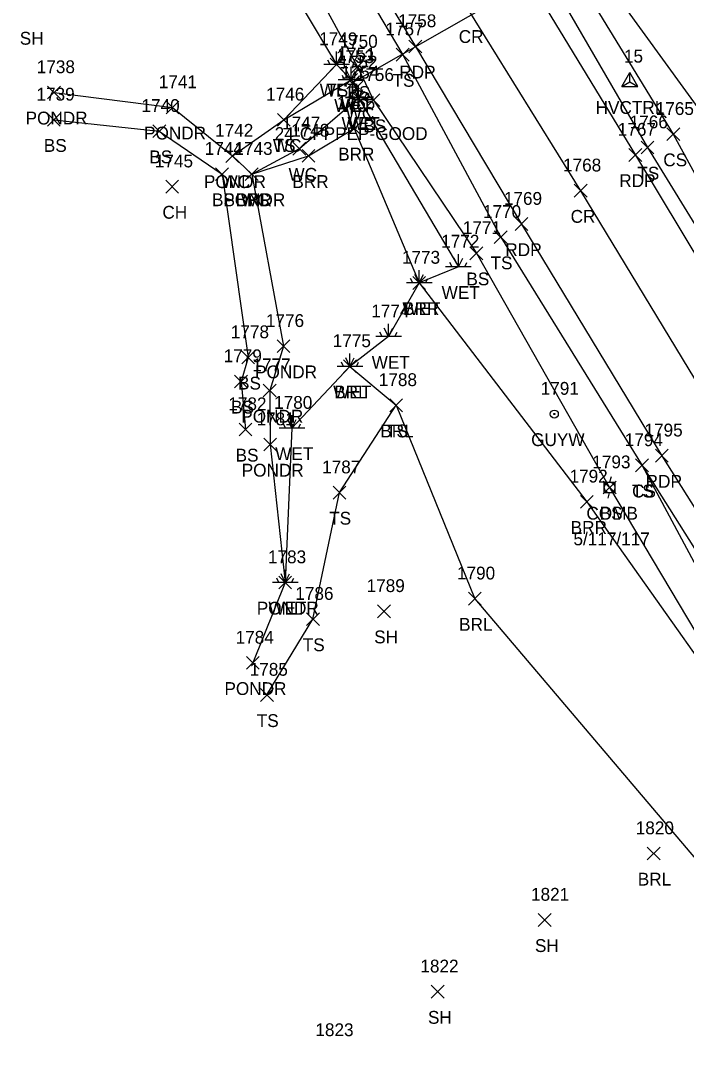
# Model space of a CAD drawing. Extents: x 1501299 to 1502485, y 381423 to 383765.
# Drawn here: x 1501313.7 to 1501417.5, y 383498.2 to 383658 of the extents above; entities that cross this region are included whole.
import ezdxf

# ---------------------------------------------------------------- set-up
doc = ezdxf.new("R2010")
doc.units = 0
for name, color, linetype in [('C_A', 7, 'Continuous'), ('C_I', 7, 'Continuous'), ('CPSM', 7, 'Continuous'), ('D_A', 7, 'Continuous'), ('D_C', 7, 'Continuous'), ('D_I', 7, 'Continuous'), ('D_TIC', 7, 'Continuous'), ('DCP', 7, 'Continuous'), ('L_A', 7, 'Continuous'), ('L_I', 7, 'Continuous'), ('L_TIC', 7, 'Continuous'), ('LABL', 7, 'Continuous'), ('LAWE', 7, 'Continuous'), ('LELB', 7, 'Continuous'), ('LWET', 7, 'Continuous'), ('P_A', 7, 'Continuous'), ('P_I', 7, 'Continuous'), ('P_TIC', 7, 'Continuous'), ('PET', 7, 'Continuous'), ('PRC', 7, 'Continuous'), ('U_A', 7, 'Continuous'), ('U_C', 7, 'Continuous'), ('U_I', 7, 'Continuous'), ('UP', 7, 'Continuous'), ('UPGW', 7, 'Continuous')]:
    doc.layers.add(name, color=color, linetype=linetype)

msp = doc.modelspace()

# ---------------------------------------------------------------- linework, layer by layer
at = {"layer": 'CPSM'}
for p, q in [((1501407.42, 383647.74), (1501408.67, 383649.91)), ((1501409.92, 383647.74), (1501408.67, 383649.91)), ((1501408.67, 383648.46), (1501408.67, 383649.91)), ((1501407.42, 383647.74), (1501408.67, 383648.46)), ((1501408.67, 383648.46), (1501408.67, 383648.46)), ((1501408.67, 383648.46), (1501409.92, 383647.74)), ((1501407.42, 383647.74), (1501409.92, 383647.74))]:
    msp.add_line(p, q, dxfattribs=at)
at = {"layer": 'D_TIC'}
for points in [[(1501364.58, 383647.39), (1501366.58, 383649.39)], [(1501366.58, 383647.39), (1501364.58, 383649.39)]]:
    msp.add_lwpolyline(points, dxfattribs=at)
at = {"layer": 'DCP'}
msp.add_lwpolyline([(1501365.58, 383648.39), (1501401.54, 383668.95)], dxfattribs=at)
at = {"layer": 'L_TIC'}
for points in [[(1501372.29, 383651.69), (1501374.29, 383653.69)], [(1501374.29, 383651.69), (1501372.29, 383653.69)], [(1501361.98, 383650.17), (1501363.98, 383652.17)], [(1501363.98, 383650.17), (1501361.98, 383652.17)], [(1501365.23, 383649.78), (1501367.23, 383651.78)], [(1501367.23, 383649.78), (1501365.23, 383651.78)], [(1501364.24, 383647.78), (1501366.24, 383649.78)], [(1501366.24, 383647.78), (1501364.24, 383649.78)], [(1501365.1, 383646.54), (1501367.1, 383648.54)], [(1501367.1, 383646.54), (1501365.1, 383648.54)], [(1501317.96, 383645.81), (1501319.96, 383647.81)], [(1501319.96, 383645.81), (1501317.96, 383647.81)], [(1501365.39, 383644.96), (1501367.39, 383646.96)], [(1501367.39, 383644.96), (1501365.39, 383646.96)], [(1501365.39, 383644.96), (1501367.39, 383646.96)], [(1501367.39, 383644.96), (1501365.39, 383646.96)], [(1501336.42, 383643.47), (1501338.42, 383645.47)], [(1501338.42, 383643.47), (1501336.42, 383645.47)], [(1501367.72, 383644.59), (1501369.72, 383646.59)], [(1501369.72, 383644.59), (1501367.72, 383646.59)], [(1501317.93, 383641.54), (1501319.93, 383643.54)], [(1501319.93, 383641.54), (1501317.93, 383643.54)], [(1501353.76, 383641.54), (1501355.76, 383643.54)], [(1501355.76, 383641.54), (1501353.76, 383643.54)], [(1501353.76, 383641.54), (1501355.76, 383643.54)], [(1501355.76, 383641.54), (1501353.76, 383643.54)], [(1501364.75, 383640.19), (1501366.75, 383642.19)], [(1501366.75, 383640.19), (1501364.75, 383642.19)], [(1501334.37, 383639.76), (1501336.37, 383641.76)], [(1501336.37, 383639.76), (1501334.37, 383641.76)], [(1501414.46, 383639.29), (1501416.46, 383641.29)], [(1501416.46, 383639.29), (1501414.46, 383641.29)], [(1501356.19, 383637.04), (1501358.19, 383639.04)], [(1501358.19, 383637.04), (1501356.19, 383639.04)], [(1501410.45, 383637.21), (1501412.45, 383639.21)], [(1501412.45, 383637.21), (1501410.45, 383639.21)], [(1501345.75, 383635.9), (1501347.75, 383637.9)], [(1501347.75, 383635.9), (1501345.75, 383637.9)], [(1501345.75, 383635.9), (1501347.75, 383637.9)], [(1501347.75, 383635.9), (1501345.75, 383637.9)], [(1501357.61, 383635.91), (1501359.61, 383637.91)], [(1501359.61, 383635.91), (1501357.61, 383637.91)], [(1501344.14, 383633.07), (1501346.14, 383635.07)], [(1501346.14, 383633.07), (1501344.14, 383635.07)], [(1501348.77, 383633.07), (1501350.77, 383635.07)], [(1501350.77, 383633.07), (1501348.77, 383635.07)], [(1501348.77, 383633.07), (1501350.77, 383635.07)], [(1501350.77, 383633.07), (1501348.77, 383635.07)], [(1501348.77, 383633.07), (1501350.77, 383635.07)], [(1501350.77, 383633.07), (1501348.77, 383635.07)], [(1501336.36, 383631.12), (1501338.36, 383633.12)], [(1501338.36, 383631.12), (1501336.36, 383633.12)], [(1501387.57, 383623.23), (1501389.57, 383625.23)], [(1501389.57, 383623.23), (1501387.57, 383625.23)], [(1501383.78, 383620.73), (1501385.78, 383622.73)], [(1501385.78, 383620.73), (1501383.78, 383622.73)], [(1501374.86, 383616.1), (1501376.86, 383618.1)], [(1501376.86, 383616.1), (1501374.86, 383618.1)], [(1501353.73, 383606.23), (1501355.73, 383608.23)], [(1501355.73, 383606.23), (1501353.73, 383608.23)], [(1501348.2, 383604.48), (1501350.2, 383606.48)], [(1501350.2, 383604.48), (1501348.2, 383606.48)], [(1501364.08, 383603.09), (1501366.08, 383605.09)], [(1501366.08, 383603.09), (1501364.08, 383605.09)], [(1501347.1, 383600.74), (1501349.1, 383602.74)], [(1501349.1, 383600.74), (1501347.1, 383602.74)], [(1501351.57, 383599.32), (1501353.57, 383601.32)], [(1501353.57, 383599.32), (1501351.57, 383601.32)], [(1501371.27, 383597.02), (1501373.27, 383599.02)], [(1501373.27, 383597.02), (1501371.27, 383599.02)], [(1501371.27, 383597.02), (1501373.27, 383599.02)], [(1501373.27, 383597.02), (1501371.27, 383599.02)], [(1501347.81, 383593.25), (1501349.81, 383595.25)], [(1501349.81, 383593.25), (1501347.81, 383595.25)], [(1501351.65, 383590.9), (1501353.65, 383592.9)], [(1501353.65, 383590.9), (1501351.65, 383592.9)], [(1501409.59, 383587.65), (1501411.59, 383589.65)], [(1501411.59, 383587.65), (1501409.59, 383589.65)], [(1501409.59, 383587.65), (1501411.59, 383589.65)], [(1501411.59, 383587.65), (1501409.59, 383589.65)], [(1501404.54, 383584.19), (1501406.54, 383586.19)], [(1501406.54, 383584.19), (1501404.54, 383586.19)], [(1501362.44, 383583.41), (1501364.44, 383585.41)], [(1501364.44, 383583.41), (1501362.44, 383585.41)], [(1501400.99, 383581.97), (1501402.99, 383583.97)], [(1501402.99, 383581.97), (1501400.99, 383583.97)], [(1501353.99, 383569.39), (1501355.99, 383571.39)], [(1501355.99, 383569.39), (1501353.99, 383571.39)], [(1501383.53, 383566.86), (1501385.53, 383568.86)], [(1501385.53, 383566.86), (1501383.53, 383568.86)], [(1501369.37, 383564.9), (1501371.37, 383566.9)], [(1501371.37, 383564.9), (1501369.37, 383566.9)], [(1501358.31, 383563.68), (1501360.31, 383565.68)], [(1501360.31, 383563.68), (1501358.31, 383565.68)], [(1501348.95, 383556.85), (1501350.95, 383558.85)], [(1501350.95, 383556.85), (1501348.95, 383558.85)], [(1501351.14, 383551.85), (1501353.14, 383553.85)], [(1501353.14, 383551.85), (1501351.14, 383553.85)], [(1501411.39, 383527.13), (1501413.39, 383529.13)], [(1501413.39, 383527.13), (1501411.39, 383529.13)], [(1501394.41, 383516.77), (1501396.41, 383518.77)], [(1501396.41, 383516.77), (1501394.41, 383518.77)], [(1501377.75, 383505.58), (1501379.75, 383507.58)], [(1501379.75, 383505.58), (1501377.75, 383507.58)]]:
    msp.add_lwpolyline(points, dxfattribs=at)
at = {"layer": 'LABL'}
for points in [[(1501349.77, 383634.07), (1501358.61, 383636.91), (1501365.75, 383641.19), (1501375.86, 383617.1), (1501401.99, 383582.97), (1501432.56, 383539.71), (1501454.75, 383505.78), (1501467.78, 383488.13), (1501464.27, 383485.42), (1501459.99, 383478.86)], [(1501365.08, 383604.09), (1501372.27, 383598.02), (1501384.53, 383567.86), (1501459.99, 383478.86)]]:
    msp.add_lwpolyline(points, dxfattribs=at)
at = {"layer": 'LAWE'}
for points in [[(1501346.75, 383636.9), (1501354.76, 383642.54), (1501365.24, 383648.78), (1501366.1, 383647.54), (1501366.39, 383645.96)], [(1501318.96, 383646.81), (1501337.42, 383644.47), (1501346.75, 383636.9), (1501349.77, 383634.07), (1501354.73, 383607.23), (1501352.57, 383600.32), (1501352.65, 383591.9), (1501354.99, 383570.39), (1501349.95, 383557.85)], [(1501349.77, 383634.07), (1501357.19, 383638.04), (1501366.39, 383645.96)]]:
    msp.add_lwpolyline(points, dxfattribs=at)
at = {"layer": 'LELB'}
for points in [[(1501358.62, 383732.98), (1501381.14, 383696.09), (1501398.69, 383667.71), (1501415.46, 383640.29), (1501435.3, 383603.99), (1501464.9, 383561.23), (1501485.32, 383525.1), (1501505.06, 383497.04), (1501522.93, 383468.15), (1501546.42, 383435.55), (1501564.6, 383407.15), (1501589.27, 383369.8), (1501600.38, 383363.76)], [(1501355.51, 383731.14), (1501378.37, 383693.86), (1501395.55, 383665.66), (1501411.45, 383638.21), (1501433.32, 383602.63), (1501461.34, 383558.64), (1501483.16, 383524.05), (1501502.07, 383494.51), (1501520.43, 383466.23), (1501542.02, 383433.96), (1501561.69, 383405.4), (1501588.28, 383366.16), (1501592.45, 383361.85)], [(1501332.79, 383719.08), (1501356.21, 383681.5), (1501373.29, 383652.69), (1501388.57, 383624.23), (1501410.59, 383588.65), (1501439.07, 383543.46), (1501460.07, 383509.46), (1501480.49, 383480.19), (1501499.63, 383452.74), (1501519.17, 383422.52), (1501533.38, 383399.88)], [(1501324.47, 383715.68), (1501351.26, 383678.54), (1501366.23, 383650.78), (1501368.72, 383645.59), (1501384.78, 383621.73), (1501405.54, 383585.19), (1501432.56, 383539.71)], [(1501354.76, 383642.54), (1501362.98, 383651.17)], [(1501318.93, 383642.54), (1501335.37, 383640.76), (1501345.14, 383634.07), (1501349.2, 383605.48), (1501348.1, 383601.74), (1501348.81, 383594.25)], [(1501352.14, 383552.85), (1501359.31, 383564.68), (1501363.44, 383584.41), (1501372.27, 383598.02)], [(1501410.59, 383588.65), (1501435.97, 383541.32), (1501457.1, 383507.19), (1501476.16, 383477.48), (1501479.31, 383471.05), (1501488.94, 383457.91)]]:
    msp.add_lwpolyline(points, dxfattribs=at)
at = {"layer": 'LWET'}
for p, q in [((1501362.98, 383651.17), (1501362.98, 383653.17)), ((1501361.98, 383651.17), (1501361.65, 383651.83)), ((1501362.98, 383651.17), (1501362.32, 383652.5)), ((1501362.98, 383651.17), (1501363.65, 383652.5)), ((1501363.98, 383651.17), (1501364.32, 383651.83)), ((1501364.98, 383651.17), (1501360.98, 383651.17)), ((1501365.24, 383648.78), (1501364.58, 383650.11)), ((1501365.24, 383648.78), (1501365.24, 383650.78)), ((1501365.24, 383648.78), (1501365.91, 383650.11)), ((1501367.24, 383648.78), (1501363.24, 383648.78)), ((1501364.24, 383648.78), (1501363.91, 383649.45)), ((1501366.24, 383648.78), (1501366.58, 383649.45)), ((1501365.39, 383645.96), (1501365.06, 383646.63)), ((1501366.39, 383645.96), (1501365.73, 383647.29)), ((1501366.39, 383645.96), (1501366.39, 383647.96)), ((1501366.39, 383645.96), (1501367.06, 383647.29)), ((1501367.39, 383645.96), (1501367.73, 383646.63)), ((1501368.39, 383645.96), (1501364.39, 383645.96)), ((1501381.98, 383619.61), (1501381.98, 383621.61)), ((1501383.98, 383619.61), (1501379.98, 383619.61)), ((1501380.98, 383619.61), (1501380.65, 383620.27)), ((1501381.98, 383619.61), (1501381.31, 383620.94)), ((1501381.98, 383619.61), (1501382.65, 383620.94)), ((1501382.98, 383619.61), (1501383.31, 383620.27)), ((1501375.86, 383617.1), (1501375.2, 383618.43)), ((1501375.86, 383617.1), (1501375.86, 383619.1)), ((1501375.86, 383617.1), (1501376.53, 383618.43)), ((1501377.86, 383617.1), (1501373.86, 383617.1)), ((1501374.86, 383617.1), (1501374.53, 383617.77)), ((1501376.86, 383617.1), (1501377.2, 383617.77)), ((1501371.09, 383608.73), (1501370.42, 383610.06)), ((1501371.09, 383608.73), (1501371.09, 383610.73)), ((1501371.09, 383608.73), (1501371.75, 383610.06)), ((1501373.09, 383608.73), (1501369.09, 383608.73)), ((1501370.09, 383608.73), (1501369.75, 383609.4)), ((1501372.09, 383608.73), (1501372.42, 383609.4)), ((1501365.08, 383604.09), (1501364.42, 383605.42)), ((1501365.08, 383604.09), (1501365.08, 383606.09)), ((1501365.08, 383604.09), (1501365.75, 383605.42)), ((1501367.08, 383604.09), (1501363.08, 383604.09)), ((1501364.08, 383604.09), (1501363.75, 383604.76)), ((1501366.08, 383604.09), (1501366.42, 383604.76)), ((1501356.04, 383594.47), (1501355.37, 383595.8)), ((1501356.04, 383594.47), (1501356.04, 383596.47)), ((1501356.04, 383594.47), (1501356.7, 383595.8)), ((1501358.04, 383594.47), (1501354.04, 383594.47)), ((1501355.04, 383594.47), (1501354.7, 383595.13)), ((1501357.04, 383594.47), (1501357.37, 383595.13)), ((1501354.99, 383570.39), (1501354.33, 383571.72)), ((1501354.99, 383570.39), (1501354.99, 383572.39)), ((1501354.99, 383570.39), (1501355.66, 383571.72)), ((1501356.99, 383570.39), (1501352.99, 383570.39)), ((1501353.99, 383570.39), (1501353.66, 383571.05)), ((1501355.99, 383570.39), (1501356.33, 383571.05))]:
    msp.add_line(p, q, dxfattribs=at)
for points in [[(1501361.86, 383735.32), (1501383.52, 383697.56), (1501401.54, 383668.95), (1501420.14, 383643.24), (1501429.42, 383625.36), (1501440.42, 383606.65), (1501468.13, 383563.3), (1501489.26, 383528.35), (1501508.23, 383499.7), (1501528.29, 383471.48), (1501550.47, 383437.33), (1501555.06, 383441.42)], [(1501320.6, 383712.99), (1501348.18, 383675.94), (1501362.98, 383651.17), (1501365.24, 383648.78)], [(1501366.39, 383645.96), (1501381.98, 383619.61), (1501375.86, 383617.1), (1501371.09, 383608.73), (1501365.08, 383604.09), (1501356.04, 383594.47), (1501354.99, 383570.39)]]:
    msp.add_lwpolyline(points, dxfattribs=at)
at = {"layer": 'P_TIC'}
for points in [[(1501374.27, 383652.98), (1501376.27, 383654.98)], [(1501376.27, 383652.98), (1501374.27, 383654.98)], [(1501408.55, 383636.05), (1501410.55, 383638.05)], [(1501410.55, 383636.05), (1501408.55, 383638.05)], [(1501400.02, 383630.48), (1501402.02, 383632.48)], [(1501402.02, 383630.48), (1501400.02, 383632.48)], [(1501390.81, 383625.28), (1501392.81, 383627.28)], [(1501392.81, 383625.28), (1501390.81, 383627.28)], [(1501412.67, 383589.16), (1501414.67, 383591.16)], [(1501414.67, 383589.16), (1501412.67, 383591.16)]]:
    msp.add_lwpolyline(points, dxfattribs=at)
at = {"layer": 'PET'}
for points in [[(1501352.61, 383730.1), (1501376.04, 383692.66), (1501392.89, 383664.45), (1501409.55, 383637.05), (1501431.22, 383601.01), (1501459.29, 383556.77), (1501480.73, 383522.39), (1501500.04, 383493.11), (1501518.67, 383465.09), (1501539.81, 383433.29), (1501559.66, 383403.85), (1501585.89, 383364.55), (1501607.04, 383333.42), (1501616.49, 383318.82), (1501608.79, 383312.41), (1501601.65, 383306.28)], [(1501334.83, 383720.25), (1501358.01, 383682.47), (1501375.27, 383653.98), (1501391.81, 383626.28), (1501413.67, 383590.16), (1501441.93, 383545.3), (1501463.31, 383511.64), (1501483.05, 383481.71), (1501501.39, 383453.56), (1501521.79, 383422.95), (1501532.7, 383406.6), (1501560.32, 383365.3), (1501580.55, 383335.85), (1501587.21, 383326.16), (1501601.65, 383306.28)]]:
    msp.add_lwpolyline(points, dxfattribs=at)
at = {"layer": 'PRC'}
msp.add_lwpolyline([(1501342.03, 383724.18), (1501367.31, 383687.9), (1501383.59, 383659.52), (1501401.02, 383631.48), (1501422.76, 383595.53), (1501451.02, 383550.58), (1501471.94, 383517.22), (1501491.45, 383487.69), (1501510.59, 383459), (1501530.12, 383428.74), (1501550.99, 383398.39), (1501579.41, 383355.49), (1501608.79, 383312.41)], dxfattribs=at)
at = {"layer": 'UP'}
for p, q in [((1501404.7, 383584.36), (1501404.7, 383586.03)), ((1501404.7, 383586.03), (1501406.37, 383586.03)), ((1501405.79, 383586.86), (1501405.54, 383586.03)), ((1501406.37, 383586.03), (1501406.37, 383584.36)), ((1501406.37, 383584.36), (1501404.7, 383584.36)), ((1501405.29, 383583.53), (1501405.54, 383584.36)), ((1501405.54, 383585.19), (1501405.54, 383585.19))]:
    msp.add_line(p, q, dxfattribs=at)
msp.add_circle((1501405.54, 383585.19), 0.833, dxfattribs=at)
at = {"layer": 'UPGW'}
for radius in [0.625, 0.0833]:
    msp.add_circle((1501396.92, 383596.66), radius, dxfattribs=at)

# ---------------------------------------------------------------- texts
at = {"layer": 'C_A'}
msp.add_text('HVCTRL', height=2, dxfattribs=at).set_placement((1501403.36, 383643.46))
at = {"layer": 'C_I'}
msp.add_text('15', height=2, dxfattribs=at).set_placement((1501407.77, 383651.46))
at = {"layer": 'D_A'}
msp.add_text('P', height=2, dxfattribs=at).set_placement((1501364.96, 383643.39))
at = {"layer": 'D_C'}
msp.add_text('24"CPPPEP-GOOD', height=2, dxfattribs=at).set_placement((1501353.34, 383639.39))
at = {"layer": 'D_I'}
msp.add_text('1753', height=2, dxfattribs=at).set_placement((1501362.89, 383651.39))
at = {"layer": 'L_A'}
for s, p in [('SH', (1501313.62, 383654.25)), ('TS', (1501371.7, 383647.69)), ('WET', (1501360.36, 383646.17)), ('TS', (1501361.39, 383646.17)), ('BS', (1501364.67, 383645.78)), ('WET', (1501362.62, 383643.78)), ('WC', (1501363.55, 383643.78)), ('PONDR', (1501314.53, 383641.81)), ('WC', (1501364.41, 383642.54)), ('WET', (1501363.77, 383640.96)), ('WC', (1501364.7, 383640.96)), ('WC', (1501364.7, 383640.96)), ('BS', (1501367.17, 383640.59)), ('PONDR', (1501332.99, 383639.47)), ('BS', (1501317.37, 383637.54)), ('WC', (1501353.06, 383637.54)), ('TS', (1501353.17, 383637.54)), ('BS', (1501333.81, 383635.76)), ('BRR', (1501363.24, 383636.19)), ('CS', (1501413.9, 383635.29)), ('PONDR', (1501342.32, 383631.9)), ('WC', (1501345.06, 383631.9)), ('WC', (1501355.5, 383633.04)), ('BRR', (1501356.1, 383631.91)), ('TS', (1501409.86, 383633.21)), ('BS', (1501343.58, 383629.07)), ('PONDR', (1501345.33, 383629.07)), ('BRR', (1501347.25, 383629.07)), ('WC', (1501348.07, 383629.07)), ('CH', (1501335.85, 383627.12)), ('TS', (1501386.98, 383619.23)), ('BS', (1501383.22, 383616.73)), ('WET', (1501379.36, 383614.61)), ('WET', (1501373.24, 383612.1)), ('BRR', (1501373.35, 383612.1)), ('WET', (1501368.46, 383603.73)), ('PONDR', (1501350.29, 383602.23)), ('BS', (1501347.64, 383600.48)), ('WET', (1501362.46, 383599.09)), ('BRL', (1501362.63, 383599.09)), ('BS', (1501346.54, 383596.74)), ('PONDR', (1501348.14, 383595.32)), ('BRL', (1501369.81, 383593.02)), ('TS', (1501370.68, 383593.02)), ('BS', (1501347.26, 383589.25)), ('WET', (1501353.42, 383589.47)), ('PONDR', (1501348.21, 383586.9)), ('TS', (1501409, 383583.65)), ('CS', (1501409.04, 383583.65)), ('TS', (1501361.84, 383579.41)), ('BS', (1501403.98, 383580.19)), ('BRR', (1501399.47, 383577.97)), ('PONDR', (1501350.56, 383565.39)), ('WET', (1501352.37, 383565.39)), ('BRL', (1501382.08, 383562.86)), ('SH', (1501368.85, 383560.9)), ('TS', (1501357.72, 383559.68)), ('PONDR', (1501345.52, 383552.85)), ('TS', (1501350.55, 383547.85)), ('BRL', (1501409.93, 383523.13)), ('SH', (1501393.9, 383512.77)), ('SH', (1501377.23, 383501.58))]:
    msp.add_text(s, height=2, dxfattribs=at).set_placement(p)
at = {"layer": 'L_I'}
for s, p in [('1749', (1501360.28, 383654.17)), ('1749', (1501360.28, 383654.17)), ('1757', (1501370.6, 383655.69)), ('1750', (1501363.45, 383653.78)), ('1751', (1501363.12, 383651.78)), ('1751', (1501363.12, 383651.78)), ('1738', (1501316.27, 383649.81)), ('1752', (1501363.41, 383650.54)), ('1754', (1501363.7, 383648.96)), ('1754', (1501363.7, 383648.96)), ('1754', (1501363.7, 383648.96)), ('1756', (1501365.98, 383648.59)), ('1741', (1501335.29, 383647.47)), ('1739', (1501316.23, 383645.54)), ('1746', (1501352.01, 383645.54)), ('1746', (1501352.01, 383645.54)), ('1740', (1501332.59, 383643.76)), ('1755', (1501363.06, 383644.19)), ('1765', (1501412.72, 383643.29)), ('1742', (1501344.06, 383639.9)), ('1742', (1501344.06, 383639.9)), ('1747', (1501354.5, 383641.04)), ('1748', (1501355.91, 383639.91)), ('1766', (1501408.66, 383641.21)), ('1744', (1501342.44, 383637.07)), ('1743', (1501347.07, 383637.07)), ('1743', (1501347.07, 383637.07)), ('1743', (1501347.07, 383637.07)), ('1745', (1501334.67, 383635.12)), ('1770', (1501385.8, 383627.23)), ('1771', (1501382.66, 383624.73)), ('1772', (1501379.29, 383622.61)), ('1773', (1501373.17, 383620.1)), ('1773', (1501373.17, 383620.1)), ('1774', (1501368.39, 383611.73)), ('1776', (1501351.98, 383610.23)), ('1778', (1501346.51, 383608.48)), ('1775', (1501362.39, 383607.09)), ('1775', (1501362.39, 383607.09)), ('1779', (1501345.4, 383604.74)), ('1777', (1501349.88, 383603.32)), ('1788', (1501369.57, 383601.02)), ('1788', (1501369.57, 383601.02)), ('1782', (1501346.12, 383597.25)), ('1780', (1501353.26, 383597.47)), ('1781', (1501350.52, 383594.9)), ('1794', (1501407.9, 383591.65)), ('1794', (1501407.9, 383591.65)), ('1787', (1501360.74, 383587.41)), ('1793', (1501402.84, 383588.19)), ('1792', (1501399.29, 383585.97)), ('1783', (1501352.3, 383573.39)), ('1783', (1501352.3, 383573.39)), ('1790', (1501381.75, 383570.86)), ('1789', (1501367.67, 383568.9)), ('1786', (1501356.56, 383567.68)), ('1784', (1501347.26, 383560.85)), ('1785', (1501349.45, 383555.85)), ('1820', (1501409.61, 383531.13)), ('1821', (1501393.29, 383520.77)), ('1822', (1501376.05, 383509.58)), ('1823', (1501359.69, 383499.65))]:
    msp.add_text(s, height=2, dxfattribs=at).set_placement(p)
at = {"layer": 'P_A'}
for s, p in [('CR', (1501382.02, 383654.52)), ('RDP', (1501372.76, 383648.98)), ('RDP', (1501407.04, 383632.05)), ('CR', (1501399.46, 383626.48)), ('RDP', (1501389.29, 383621.28)), ('RDP', (1501411.15, 383585.16))]:
    msp.add_text(s, height=2, dxfattribs=at).set_placement(p)
at = {"layer": 'P_I'}
for s, p in [('1758', (1501372.58, 383656.98)), ('1767', (1501406.81, 383640.05)), ('1768', (1501398.28, 383634.48)), ('1769', (1501389.06, 383629.28)), ('1795', (1501410.97, 383593.16))]:
    msp.add_text(s, height=2, dxfattribs=at).set_placement(p)
at = {"layer": 'U_A'}
for s, p in [('GUYW', (1501393.31, 383591.66)), ('COMB', (1501401.92, 383580.19))]:
    msp.add_text(s, height=2, dxfattribs=at).set_placement(p)
at = {"layer": 'U_C'}
msp.add_text('5/117/117', height=2, dxfattribs=at).set_placement((1501399.9, 383576.19))
at = {"layer": 'U_I'}
for s, p in [('1791', (1501394.8, 383599.66)), ('1793', (1501402.84, 383588.19))]:
    msp.add_text(s, height=2, dxfattribs=at).set_placement(p)

doc.saveas('drawing.dxf')
